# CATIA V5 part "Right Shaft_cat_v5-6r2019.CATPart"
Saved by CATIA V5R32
Part number: Right hand shaft
Bounding box of the stored display mesh (mm): x 0 to 100, y -35 to 35, z -35 to 35
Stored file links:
  D:\PROJECTS\Project 2022\CATIA V5 6R 2022\Resources\Tutorial Files\c16_catia_v5_6r2022_tut\CV joint\Right Shaft_cat_v5-6r2019.CATPart
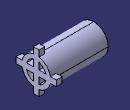
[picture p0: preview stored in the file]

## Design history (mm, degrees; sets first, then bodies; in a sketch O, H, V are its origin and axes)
Body1 (main body)
  Sketch1 on yz-plane, origin (0, 0, 0), H (0, 1, 0), V (0, 0, 1)
    circle A1 centre (0, 0) radius 25
    circle A2 centre (0, 0) radius 17.5
    radius A1 = 25
    radius A2 = 17.5
  Pad1: profile Sketch1, direction (1, 0, 0), length 100
  Sketch2 on end face of Pad1, origin (100, 0, 0), H (0, 1, 0), V (0, 0, 1)
    line L1 (5, 35) -> (5, -35)
    line L2 (5, -35) -> (-5, -35)
    line L3 (-5, -35) -> (-5, 35)
    line L4 (-5, 35) -> (5, 35)
    length L1 = 70
    length L4 = 10
    vertical: L1 V, L3 V
    horizontal: L2 H, L4 H
    equidistance: L1 L3 O, L2 L4 O
  Pad2: profile Sketch2, direction (-1, 0, 0), length 10
  CircPattern1: of the body so far, instances 2, angular step 90, axis from face of Pad1 from Sketch1.A1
